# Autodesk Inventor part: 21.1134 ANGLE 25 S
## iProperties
Created: 2007-01
Part Number: 21.1134 ANGLE 25 S
Document SubType Name: Modeling
Designer: Andy Moles
Material: Aluminum-6061
Density: 2.71 g/cm^3
Author: Andy Moles
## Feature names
1. Base1
